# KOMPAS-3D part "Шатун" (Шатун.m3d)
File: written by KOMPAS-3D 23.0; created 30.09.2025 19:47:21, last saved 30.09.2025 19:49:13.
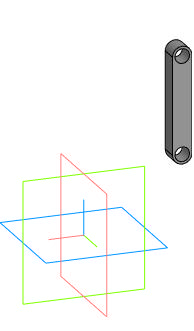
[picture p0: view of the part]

Document properties: Автор: Inspektor_Kot; Полное имя файла: I:\Autodesk Inventor Projects\ИМ-ИТ ЦД\Вариант 6\Шатун.m3d

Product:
- Part/product: Шатун
    Масса: 0.019717

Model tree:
1. Эскиз:1  (with: Элемент выдавливания:1, Элемент выдавливания:2)  (labels: I:\Autodesk Inventor Projects\ИМ-ИТ ЦД\Вариант 6\Шатун.a3d)
2. Элемент выдавливания:1
     Расстояние 1 = 8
